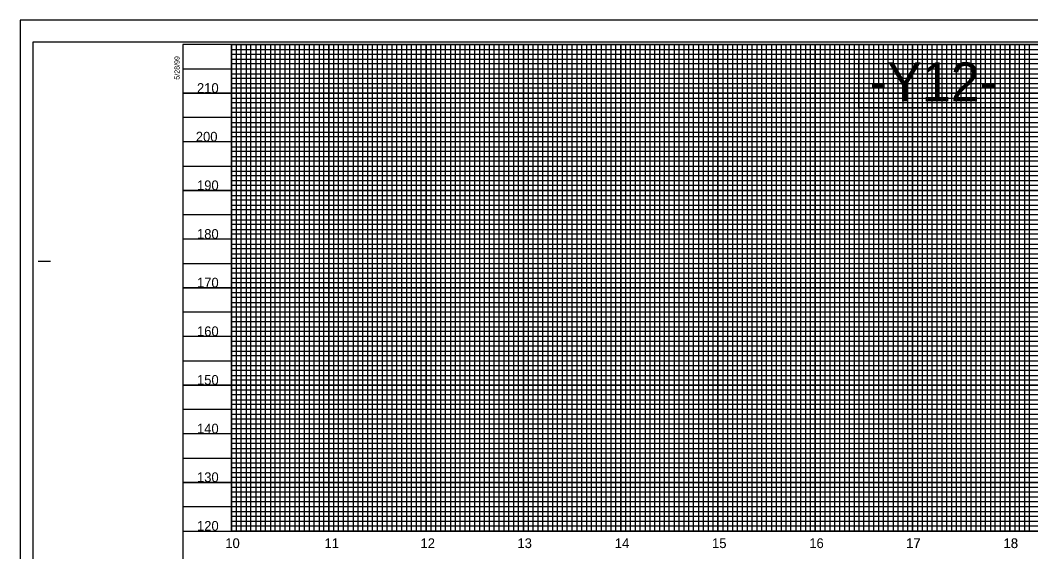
# Model space of a CAD drawing. Extents: x 1779926 to 1781610, y 605564 to 621564.
# Drawn here: x 1779926 to 1780964, y 606118 to 606664 of the extents above; entities that cross this region are included whole.
import ezdxf

# ---------------------------------------------------------------- set-up
doc = ezdxf.new("R2010")
doc.units = 0
for name, color, linetype in [('Exist Vertical Profile Horizontal Axis Label Major', 7, 'Continuous'), ('Exist Vertical Profile Vertical Axis Label', 7, 'Continuous'), ('Prop Grid Mask', 7, 'Continuous'), ('Scratch_Level_0', 7, 'Continuous'), ('Sheet DOT Grid CELL', 7, 'Continuous'), ('Sheet Layout Profile Border Port 1', 7, 'Continuous'), ('Sheet Plot Border Inside CELL', 7, 'Continuous'), ('Sheet Plot Border Outside CELL', 7, 'Continuous'), ('Sheet Profile CELL', 7, 'Continuous'), ('Sheet Profile Grid Major CELL', 7, 'Continuous'), ('Sheet Profile Grid Middle CELL', 7, 'Continuous'), ('Sheet Profile Grid Minor CELL', 7, 'Continuous')]:
    doc.layers.add(name, color=color, linetype=linetype)

msp = doc.modelspace()

# ---------------------------------------------------------------- linework, layer by layer
at = {"layer": 'Prop Grid Mask'}
msp.add_lwpolyline([(1780787.8, 606624.2), (1780943, 606624.2), (1780943, 606574.2), (1780787.8, 606574.2)], close=True, dxfattribs=at)
at = {"layer": 'Scratch_Level_0'}
msp.add_lwpolyline([(1780143, 606139.2), (1780143, 606639.2), (1781393, 606639.2), (1781393, 606414.2), (1781543, 606414.2), (1781543, 606139.2)], close=True, dxfattribs=at)
at = {"layer": 'Sheet DOT Grid CELL'}
for p, q in [((1780143, 606139.2), (1780143, 606639.2)), ((1780193, 606139.2), (1780193, 606639.2)), ((1780243, 606139.2), (1780243, 606639.2)), ((1780293, 606139.2), (1780293, 606639.2)), ((1780343, 606139.2), (1780343, 606639.2)), ((1780393, 606139.2), (1780393, 606639.2)), ((1780443, 606139.2), (1780443, 606639.2)), ((1780493, 606139.2), (1780493, 606639.2)), ((1780543, 606139.2), (1780543, 606639.2)), ((1780593, 606139.2), (1780593, 606639.2)), ((1780643, 606139.2), (1780643, 606639.2)), ((1780693, 606139.2), (1780693, 606639.2)), ((1780743, 606139.2), (1780743, 606639.2)), ((1780793, 606139.2), (1780793, 606639.2)), ((1780843, 606139.2), (1780843, 606639.2)), ((1780893, 606139.2), (1780893, 606639.2)), ((1780943, 606139.2), (1780943, 606639.2)), ((1781392.9, 606589.2), (1780093, 606589.2)), ((1781392.9, 606539.2), (1780093, 606539.2)), ((1781393, 606489.2), (1780093, 606489.2)), ((1781392.9, 606439.2), (1780093, 606439.2)), ((1781593, 606389.2), (1780093, 606389.2)), ((1781593, 606339.2), (1780093, 606339.2)), ((1781593, 606289.2), (1780093, 606289.2)), ((1781593, 606239.2), (1780093, 606239.2)), ((1781593, 606189.2), (1780093, 606189.2))]:
    msp.add_line(p, q, dxfattribs=at)
at = {"layer": 'Sheet Layout Profile Border Port 1'}
msp.add_lwpolyline([(1780143, 606639.2), (1781392.9, 606639.2), (1781392.9, 606414.2), (1781543, 606414.2), (1781543, 606139.2), (1780143, 606139.2)], close=True, dxfattribs=at)
msp.add_lwpolyline([(1780143, 606478.2), (1780143, 606139.2), (1781543, 606139.2), (1781543, 606414.2)], dxfattribs=at)
at = {"layer": 'Sheet Plot Border Inside CELL'}
msp.add_lwpolyline([(1779939, 605586.7), (1781605.5, 605586.7), (1781605.5, 606641.8), (1779939, 606641.8)], close=True, dxfattribs=at)
at = {"layer": 'Sheet Plot Border Outside CELL'}
msp.add_lwpolyline([(1779926, 605564.2), (1781610, 605564.2), (1781610, 606664.2), (1779926, 606664.2)], close=True, dxfattribs=at)
at = {"layer": 'Sheet Profile CELL'}
for p, q in [((1779944.5, 606416.7), (1779957, 606416.7)), ((1780093, 606139.2), (1781593, 606139.2))]:
    msp.add_line(p, q, dxfattribs=at)
msp.add_lwpolyline([(1781593, 606639.2), (1780093, 606639.2), (1780093, 605589.2), (1781593, 605589.2)], close=True, dxfattribs=at)
at = {"layer": 'Sheet Profile Grid Major CELL'}
for points in [[(1780143, 606639.2), (1780143, 606139.2), (1780193, 606139.2), (1780193, 606639.2), (1780243, 606639.2), (1780243, 606139.2), (1780293, 606139.2), (1780293, 606639.2), (1780343, 606639.2), (1780343, 606139.2), (1780393, 606139.2), (1780393, 606639.2), (1780443, 606639.2), (1780443, 606139.2), (1780493, 606139.2), (1780493, 606639.2), (1780543, 606639.2), (1780543, 606139.2), (1780593, 606139.2), (1780593, 606639.2), (1780643, 606639.2), (1780643, 606139.2), (1780693, 606139.2), (1780693, 606639.2), (1780743, 606639.2), (1780743, 606139.2), (1780793, 606139.2), (1780793, 606639.2), (1780843, 606639.2), (1780843, 606139.2), (1780893, 606139.2), (1780893, 606639.2), (1780943, 606639.2), (1780943, 606139.2), (1780993, 606139.2)], [(1780093, 606589.2), (1781393, 606589.2)], [(1781393, 606539.2), (1780093, 606539.2), (1780093, 606489.2), (1781393, 606489.2)], [(1781392.9, 606439.2), (1780093, 606439.2), (1780093, 606389.2), (1781593, 606389.2)], [(1781593, 606339.2), (1780093, 606339.2), (1780093, 606289.2), (1781593, 606289.2)], [(1781593, 606239.2), (1780093, 606239.2), (1780093, 606239.2), (1780093, 606189.2), (1781593, 606189.2)]]:
    msp.add_lwpolyline(points, dxfattribs=at)
at = {"layer": 'Sheet Profile Grid Middle CELL'}
msp.add_line((1780093, 606614.2), (1781392.9, 606614.2), dxfattribs=at)
for points in [[(1780168, 606639.2), (1780168, 606139.2), (1780218, 606139.2), (1780218, 606639.2), (1780268, 606639.2), (1780268, 606139.2), (1780318, 606139.2), (1780318, 606639.2), (1780368, 606639.2), (1780368, 606139.2), (1780418, 606139.2), (1780418, 606639.2), (1780468, 606639.2), (1780468, 606139.2), (1780518, 606139.2), (1780518, 606639.2), (1780568, 606639.2), (1780568, 606139.2), (1780618, 606139.2), (1780618, 606639.2), (1780668, 606639.2), (1780668, 606139.2), (1780718, 606139.2), (1780718, 606139.2), (1780718, 606639.2), (1780768, 606639.2), (1780768, 606139.2), (1780818, 606139.2), (1780818, 606639.2), (1780868, 606639.2), (1780868, 606139.2), (1780918, 606139.2), (1780918, 606639.2), (1780968, 606639.2)], [(1781393, 606564.2), (1780093, 606564.2), (1780093, 606514.2), (1781393, 606514.2)], [(1781392.9, 606464.2), (1780093, 606464.2), (1780093, 606414.2), (1781418, 606414.2)], [(1781593, 606364.2), (1780093, 606364.2), (1780093, 606314.2), (1781593, 606314.2)], [(1781593, 606264.2), (1780093, 606264.2), (1780093, 606214.2), (1781593, 606214.2)], [(1781593, 606164.2), (1780093, 606164.2)]]:
    msp.add_lwpolyline(points, dxfattribs=at)
at = {"layer": 'Sheet Profile Grid Minor CELL'}
for p, q in [((1780143, 606634.2), (1781393, 606634.2)), ((1780143, 606629.2), (1780143, 606629.2)), ((1781393, 606629.2), (1780143, 606628.9)), ((1780143, 606624.2), (1781393, 606624.2)), ((1781392.9, 606504.2), (1780143, 606504.2)), ((1781393, 606499.2), (1780143, 606499.2)), ((1781393, 606494.2), (1780143, 606494.2)), ((1780143, 606484.2), (1781393, 606484.2)), ((1781393, 606479.2), (1780143, 606479.2)), ((1780143, 606474.2), (1781393, 606474.2)), ((1781393, 606454.2), (1780143, 606454.2)), ((1780143, 606449.2), (1781393, 606449.2)), ((1781392.9, 606429.2), (1780143, 606429.2)), ((1780143, 606424.2), (1781392.9, 606424.2)), ((1781543, 606404.2), (1780143, 606404.2)), ((1780143, 606399.2), (1781543, 606399.2)), ((1781543, 606394.2), (1780143, 606394.2)), ((1780143, 606384.2), (1781543, 606384.2)), ((1781543, 606379.2), (1780143, 606379.2)), ((1780143, 606374.2), (1781543, 606374.2)), ((1781543, 606369.2), (1780143, 606369.2)), ((1780143, 606359.2), (1781543, 606359.2)), ((1781543, 606354.2), (1780143, 606354.2)), ((1780143, 606349.2), (1781543, 606349.2)), ((1781543, 606344.2), (1780143, 606344.2)), ((1780143, 606334.2), (1781543, 606334.2)), ((1781543, 606329.2), (1780143, 606329.2)), ((1780143, 606324.2), (1781543, 606324.2)), ((1781543, 606319.2), (1780143, 606319.2)), ((1780143, 606309.2), (1781543, 606309.2)), ((1781543, 606304.2), (1780143, 606304.2)), ((1780143, 606299.2), (1781543, 606299.2)), ((1781543, 606294.2), (1780143, 606294.2)), ((1780143, 606284.2), (1781543, 606284.2)), ((1781543, 606279.2), (1780143, 606279.2)), ((1780143, 606274.2), (1781543, 606274.2)), ((1781543, 606269.2), (1780143, 606269.2)), ((1780143, 606259.2), (1781543, 606259.2)), ((1781543, 606254.2), (1780143, 606254.2)), ((1781543, 606249.2), (1780143, 606249.2)), ((1781543, 606244.2), (1780143, 606244.2)), ((1780143, 606234.2), (1781543, 606234.2)), ((1781543, 606229.2), (1780143, 606229.2)), ((1780143, 606224.2), (1781543, 606224.2)), ((1781543, 606219.2), (1780143, 606219.2)), ((1780143, 606209.2), (1781543, 606209.2)), ((1781543, 606204.2), (1780143, 606204.2)), ((1780143, 606199.2), (1781543, 606199.2)), ((1781543, 606194.2), (1780143, 606194.2)), ((1780143, 606184.2), (1781543, 606184.2)), ((1781543, 606179.2), (1780143, 606179.2)), ((1780143, 606174.2), (1781543, 606174.2)), ((1781543, 606169.2), (1780143, 606169.2)), ((1780143, 606159.2), (1781543, 606159.2)), ((1781543, 606154.2), (1780143, 606154.2)), ((1780143, 606149.2), (1781543, 606149.2))]:
    msp.add_line(p, q, dxfattribs=at)
for points in [[(1780148, 606639.2), (1780148, 606139.2), (1780153, 606139.2), (1780153, 606639.2), (1780158, 606639.2), (1780158, 606139.2), (1780163, 606139.2), (1780163, 606639.2), (1780173, 606639.2), (1780173, 606139.2), (1780178, 606139.2), (1780178, 606639.2), (1780183, 606639.2), (1780183, 606139.2), (1780188, 606139.2), (1780198, 606139.2), (1780203, 606139.2), (1780203, 606639.2), (1780208, 606639.2), (1780208, 606139.2), (1780213, 606139.2), (1780213, 606639.2), (1780223, 606639.2), (1780223, 606139.2), (1780228, 606139.2), (1780228, 606639.2), (1780233, 606639.2), (1780233, 606139.2), (1780238, 606139.2), (1780238, 606639.2), (1780248, 606639.2), (1780248, 606139.2), (1780253, 606139.2), (1780253, 606639.2), (1780258, 606639.2), (1780258, 606139.2), (1780263, 606139.2), (1780263, 606639.2), (1780273, 606639.2), (1780273, 606139.2), (1780278, 606139.2), (1780278, 606639.2), (1780283, 606639.2), (1780283, 606139.2), (1780288, 606139.2), (1780288, 606639.2), (1780298, 606639.2), (1780298, 606139.2), (1780303, 606139.2), (1780303, 606639.2), (1780308, 606639.2), (1780308, 606139.2), (1780313, 606139.2), (1780313, 606639.2), (1780323, 606639.2), (1780323, 606139.2), (1780328, 606139.2), (1780328, 606639.2), (1780333, 606639.2), (1780333, 606139.2), (1780338, 606139.2), (1780338, 606639.2), (1780348, 606639.2), (1780348, 606139.2), (1780353, 606139.2), (1780353, 606639.2), (1780358, 606639.2), (1780358, 606139.2)], [(1780188, 606139.2), (1780188, 606639.2), (1780198, 606639.2), (1780198, 606139.2)], [(1780358, 606139.2), (1780363, 606139.2), (1780363, 606639.2), (1780373, 606639.2), (1780373, 606139.2), (1780378, 606139.2), (1780378, 606639.2), (1780383, 606639.2), (1780383, 606139.2), (1780388, 606139.2), (1780388, 606639.2), (1780398, 606639.2), (1780398, 606139.2), (1780403, 606139.2), (1780403, 606639.2), (1780408, 606639.2), (1780408, 606139.2), (1780413, 606139.2), (1780413, 606639.2), (1780423, 606639.2), (1780423, 606139.2), (1780428, 606139.2), (1780428, 606639.2), (1780433, 606639.2), (1780433, 606139.2), (1780438, 606139.2), (1780438, 606639.2), (1780448, 606639.2), (1780448, 606139.2), (1780453, 606139.2), (1780453, 606639.2), (1780458, 606639.2), (1780458, 606139.2), (1780463, 606139.2), (1780463, 606639.2), (1780473, 606639.2), (1780473, 606139.2), (1780478, 606139.2), (1780478, 606639.2), (1780483, 606639.2), (1780483, 606139.2), (1780488, 606139.2), (1780488, 606639.2), (1780498, 606639.2), (1780498, 606139.2), (1780503, 606139.2), (1780503, 606639.2), (1780508, 606639.2), (1780508, 606139.2), (1780513, 606139.2), (1780513, 606639.2), (1780523, 606639.2), (1780523, 606139.2), (1780528, 606139.2), (1780528, 606639.2), (1780533, 606639.2), (1780533, 606139.2), (1780538, 606139.2), (1780538, 606639.2), (1780548, 606639.2), (1780548, 606139.2), (1780553, 606139.2), (1780553, 606639.2), (1780558, 606639.2), (1780558, 606139.2), (1780563, 606139.2), (1780563, 606639.2), (1780573, 606639.2), (1780573, 606139.2), (1780578, 606139.2), (1780578, 606639.2), (1780583, 606639.2), (1780583, 606139.2), (1780588, 606139.2), (1780588, 606639.2), (1780598, 606639.2), (1780598, 606139.2), (1780603, 606139.2), (1780603, 606639.2), (1780608, 606639.2), (1780608, 606139.2), (1780613, 606139.2), (1780613, 606639.2), (1780623, 606639.2), (1780623, 606139.2), (1780628, 606139.2), (1780628, 606639.2), (1780633, 606639.2), (1780633, 606139.2), (1780638, 606139.2), (1780638, 606639.2), (1780648, 606639.2), (1780648, 606139.2), (1780653, 606139.2), (1780653, 606639.2), (1780658, 606639.2), (1780658, 606139.2), (1780663, 606139.2), (1780663, 606639.2), (1780673, 606639.2)], [(1780673, 606639.2), (1780673, 606139.2), (1780678, 606139.2), (1780678, 606639.2), (1780683, 606639.2), (1780683, 606139.2), (1780688, 606139.2), (1780688, 606639.2), (1780698, 606639.2), (1780698, 606139.2), (1780703, 606139.2), (1780703, 606639.2), (1780708, 606639.2), (1780708, 606139.2), (1780713, 606139.2), (1780713, 606639.2), (1780723, 606639.2), (1780723, 606139.2), (1780728, 606139.2), (1780728, 606639.2), (1780733, 606639.2), (1780733, 606139.2), (1780738, 606139.2), (1780738, 606639.2), (1780748, 606639.2), (1780748, 606139.2), (1780753, 606139.2), (1780753, 606639.2), (1780758, 606639.2), (1780758, 606139.2), (1780763, 606139.2), (1780763, 606639.2), (1780773, 606639.2), (1780773, 606139.2), (1780778, 606139.2), (1780778, 606639.2), (1780783, 606639.2), (1780783, 606139.2), (1780788, 606139.2), (1780788, 606639.2), (1780798, 606639.2), (1780798, 606139.2), (1780798, 606139.2), (1780803, 606139.2), (1780803, 606639.2), (1780808, 606639.2), (1780808, 606139.2), (1780813, 606139.2), (1780813, 606639.2), (1780823, 606639.2), (1780823, 606139.2), (1780828, 606139.2), (1780828, 606639.2), (1780833, 606639.2), (1780833, 606139.2), (1780838, 606139.2), (1780838, 606639.2), (1780848, 606639.2), (1780848, 606139.2), (1780853, 606139.2), (1780853, 606639.2), (1780858, 606639.2), (1780858, 606139.2), (1780863, 606139.2), (1780863, 606639.2), (1780873, 606639.2), (1780873, 606139.2), (1780878, 606139.2), (1780878, 606639.2), (1780883, 606639.2), (1780883, 606139.2), (1780888, 606139.2), (1780888, 606639.2), (1780898, 606639.2), (1780898, 606139.2), (1780903, 606139.2), (1780903, 606639.2), (1780908, 606639.2), (1780908, 606139.2), (1780913, 606139.2), (1780913, 606639.2), (1780923, 606639.2), (1780923, 606139.2), (1780928, 606139.2), (1780928, 606639.2), (1780933, 606639.2), (1780933, 606139.2), (1780938, 606139.2), (1780938, 606639.2), (1780948, 606639.2), (1780948, 606139.2), (1780952.7, 606139.8), (1780953, 606139.2), (1780953, 606639.2), (1780958, 606639.2), (1780958, 606139.2), (1780963, 606139.2), (1780963, 606639.2), (1780973, 606639.2)], [(1781393, 606619.2), (1780143, 606619.2), (1780143, 606609.2), (1781393, 606609.2)], [(1781392.9, 606604.2), (1780143, 606604.2), (1780143, 606599.2), (1781393, 606599.2)], [(1781393, 606594.2), (1780143, 606594.2), (1780143, 606584.2), (1781393, 606584.2)], [(1781393, 606579.2), (1780143, 606579.2), (1780143, 606574.2), (1781393, 606574.2)], [(1781393, 606569.2), (1780143, 606569.2), (1780143, 606559.2), (1781393, 606559.2)], [(1781393, 606554.2), (1780143, 606554.2), (1780143, 606549.2), (1781393, 606549.2)], [(1781393, 606544.2), (1780143, 606544.2), (1780143, 606534.2), (1781393, 606534.2)], [(1781393, 606529.1), (1780143.1, 606529.1), (1780143.1, 606524.2), (1781393, 606524.2)], [(1781393, 606519.2), (1780143, 606519.2), (1780143, 606509.2), (1781393, 606509.2)], [(1781392.9, 606469.2), (1780143, 606469.2), (1780143, 606459.2), (1781392.9, 606459.2)], [(1781392.9, 606444.2), (1780143, 606444.2), (1780143, 606434.2), (1781392.9, 606434.2)], [(1781392.9, 606419.2), (1780143, 606419.2), (1780143, 606409.2), (1781543, 606409.2)], [(1781543, 606144.2), (1780143, 606144.2)]]:
    msp.add_lwpolyline(points, dxfattribs=at)

# ---------------------------------------------------------------- texts
at = {"layer": 'Exist Vertical Profile Horizontal Axis Label Major'}
for s, p in [('10', (1780136.7, 606121.7)), ('11', (1780238.7, 606121.7)), ('12', (1780337.3, 606121.7)), ('13', (1780436.9, 606121.7)), ('14', (1780537, 606121.7)), ('15', (1780636.9, 606121.7)), ('16', (1780736.8, 606121.7)), ('17', (1780836.2, 606121.7)), ('17', (1780836.2, 606121.7)), ('17', (1780836.5, 606121.7)), ('18', (1780936.4, 606121.7)), ('18', (1780936.4, 606121.7)), ('18', (1780936.6, 606121.7))]:
    msp.add_text(s, height=10, dxfattribs=at).set_placement(p)
at = {"layer": 'Exist Vertical Profile Vertical Axis Label'}
for s, height, p in [('-Y12-', 40, (1780799, 606580.8)), ('210', 10, (1780107.6, 606589.5)), ('200', 10, (1780106.4, 606539.5)), ('190', 10, (1780107.6, 606489.5)), ('180', 10, (1780107.6, 606439.5)), ('170', 10, (1780107.6, 606389.5)), ('160', 10, (1780107.6, 606339.5)), ('150', 10, (1780107.6, 606289.5)), ('140', 10, (1780107.6, 606239.5)), ('130', 10, (1780107.6, 606189.5)), ('120', 10, (1780107.6, 606139.5))]:
    msp.add_text(s, height=height, dxfattribs=at).set_placement(p)
at = {"layer": 'Sheet Profile CELL'}
msp.add_text('5/28/99', height=5.25, rotation=90, dxfattribs=at).set_placement((1780089.7, 606603.1))

doc.saveas('drawing.dxf')
